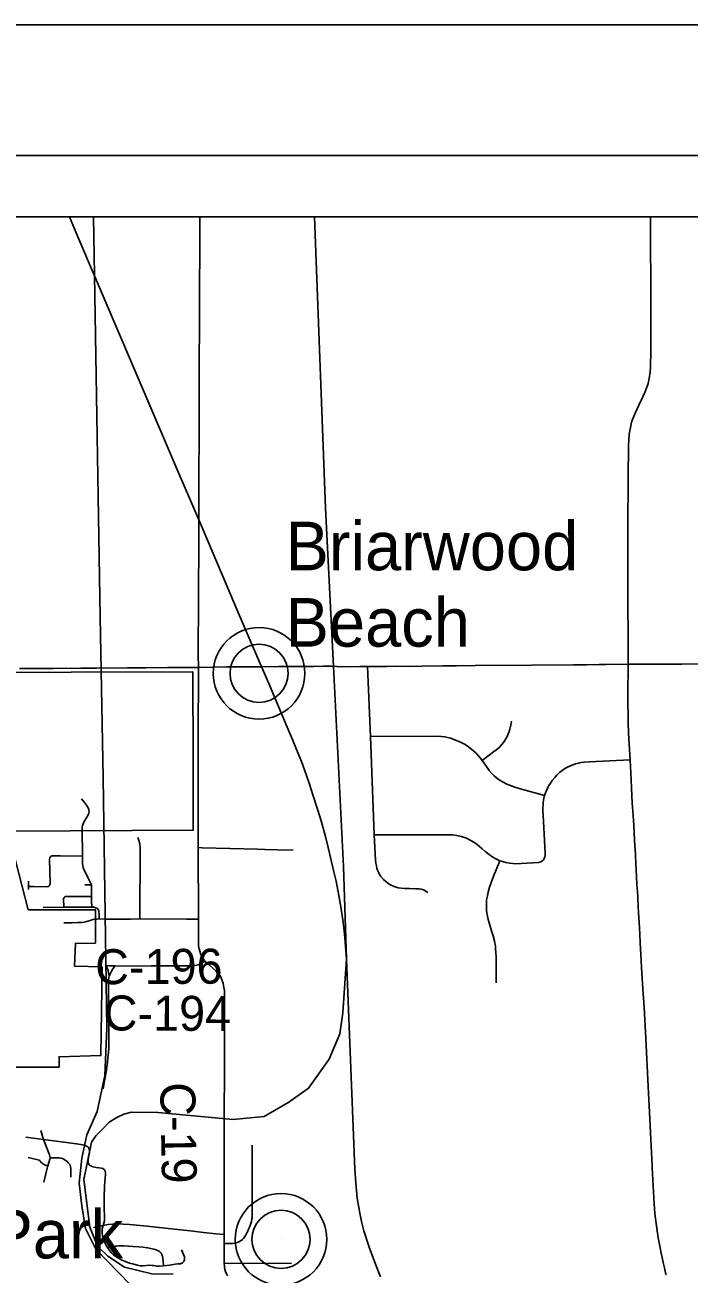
# Model space of a CAD drawing. Extents: x 0 to 34, y 0 to 22.
# Drawn here: x 24.319 to 25.398, y 8.747 to 10.777 of the extents above; entities that cross this region are included whole.
import ezdxf

# ---------------------------------------------------------------- set-up
doc = ezdxf.new("R2010")
doc.units = 0
for name, color, linetype in [('GM_X_Corporation', 7, 'Continuous'), ('GM_X_County_Road', 7, 'Continuous'), ('GM_X_County_Road_Text', 7, 'Continuous'), ('GM_X_Rail_Line', 7, 'Continuous'), ('GM_X_Township_Road', 7, 'Continuous'), ('GM_X_Unincorporated', 7, 'Continuous'), ('GM_X_Unincorporated_Location', 7, 'Continuous'), ('GM_X_Unincorporated_Text', 7, 'Continuous'), ('SH_Data', 7, 'Continuous')]:
    doc.layers.add(name, color=color, linetype=linetype)

msp = doc.modelspace()

# ---------------------------------------------------------------- linework, layer by layer
at = {"layer": 'GM_X_Corporation'}
for points in [[(23.9985, 9.7237), (24.5914, 9.7256), (24.5919, 9.5817), (24.5922, 9.4678), (24.2928, 9.4662)], [(24.2932, 9.4586), (24.3242, 9.3384), (24.4333, 9.3387), (24.4333, 9.2845), (24.401, 9.2841), (24.3995, 9.2472), (24.4443, 9.2458), (24.4421, 9.1017), (24.3743, 9.0997), (24.3743, 9.083), (24.3, 9.083)]]:
    msp.add_lwpolyline(points, dxfattribs=at)
at = {"layer": 'GM_X_County_Road'}
for points in [[(24.6008, 9.8433), (24.6012, 9.943), (24.6012, 9.9715), (24.6017, 10.1839), (24.6025, 10.3332), (24.6027, 10.427), (24.6029, 10.4647)], [(24.6008, 9.7322), (24.6005, 9.7536), (24.6008, 9.8433)], [(24.3101, 9.7306), (24.3258, 9.7307), (24.3649, 9.7308), (24.4097, 9.7312), (24.4179, 9.7313), (24.4352, 9.7313), (24.4856, 9.7319), (24.5155, 9.7321), (24.5502, 9.7323), (24.5828, 9.7322), (24.6008, 9.7322)], [(24.6005, 9.4751), (24.6003, 9.5159), (24.6004, 9.5367), (24.6001, 9.5728), (24.6005, 9.6619), (24.6008, 9.6877), (24.6008, 9.7322)], [(24.6008, 9.7322), (24.6468, 9.7334), (24.6603, 9.7335), (24.6752, 9.7335), (24.6891, 9.7336), (24.7035, 9.7337), (24.7312, 9.7339), (24.7598, 9.7341), (24.7879, 9.7343), (24.8037, 9.7344), (24.8172, 9.7345), (24.8337, 9.7336), (24.8628, 9.7338), (24.8755, 9.7339), (24.9068, 9.7342), (24.9214, 9.7344), (24.944, 9.7343), (24.9636, 9.7347), (24.9969, 9.7351), (25.0198, 9.7352), (25.0503, 9.7354), (25.1423, 9.736), (25.21, 9.7367), (25.2316, 9.737), (25.2518, 9.7371), (25.2632, 9.7372), (25.2989, 9.7376)], [(25.2989, 9.7376), (25.386, 9.7377), (25.561, 9.7385), (25.5754, 9.7381), (25.577, 9.738), (25.5786, 9.7378), (25.5801, 9.7377), (25.5817, 9.7375), (25.5833, 9.7372), (25.5848, 9.737), (25.5864, 9.7367), (25.5879, 9.7364), (25.5894, 9.7361), (25.591, 9.7357), (25.5925, 9.7353), (25.5947, 9.735), (25.5959, 9.7349)], [(24.6481, 8.7439), (24.6465, 8.7469), (24.6449, 8.7508), (24.6438, 8.7542), (24.6431, 8.7571), (24.6429, 8.7592), (24.6426, 8.7635), (24.6423, 8.7802), (24.6424, 8.796), (24.6423, 8.8107), (24.6424, 8.872), (24.6426, 9.0037), (24.6429, 9.0795), (24.6431, 9.1702), (24.643, 9.2), (24.6428, 9.2073), (24.6422, 9.2121), (24.641, 9.2186), (24.6394, 9.2236), (24.6384, 9.2262), (24.6369, 9.2294), (24.6348, 9.2324), (24.6329, 9.235), (24.6307, 9.2375), (24.6287, 9.2395), (24.6241, 9.2435), (24.619, 9.248), (24.611, 9.2553), (24.6077, 9.26), (24.6062, 9.2628), (24.6041, 9.2676), (24.6028, 9.2713), (24.6018, 9.2744), (24.6012, 9.2775), (24.6009, 9.2803), (24.6008, 9.3094), (24.6008, 9.3234), (24.6005, 9.4397), (24.6005, 9.4751)], [(24.3823, 9.3173), (24.3955, 9.3174), (24.4049, 9.3177), (24.4105, 9.318), (24.4151, 9.3186), (24.4192, 9.3196), (24.4262, 9.3219), (24.4293, 9.3227), (24.432, 9.3232)], [(24.432, 9.3232), (24.4324, 9.3233), (24.4358, 9.3236), (24.4396, 9.3237), (24.4511, 9.3236), (24.4712, 9.3233), (24.4904, 9.3236), (24.5056, 9.3237), (24.5812, 9.3236), (24.6008, 9.3234)], [(24.4509, 9.2479), (24.4564, 9.2475), (24.4606, 9.2474), (24.4656, 9.2473), (24.5025, 9.2472), (24.524, 9.2474), (24.5914, 9.2478), (24.5949, 9.2481), (24.598, 9.2486), (24.6004, 9.2493), (24.6027, 9.2502), (24.6046, 9.2514), (24.611, 9.2553)]]:
    msp.add_lwpolyline(points, dxfattribs=at)
at = {"layer": 'GM_X_Rail_Line'}
msp.add_line((24.4318, 10.3698), (24.4302, 10.4647), dxfattribs=at)
for points in [[(24.8962, 8.7422), (24.8883, 8.7629), (24.8781, 8.7904), (24.8693, 8.8167), (24.8654, 8.832), (24.8627, 8.8454), (24.8588, 8.8698), (24.8565, 8.895), (24.855, 8.9173), (24.8414, 9.2584), (24.8382, 9.2995), (24.8365, 9.3144), (24.8343, 9.3292), (24.832, 9.3436), (24.8286, 9.3621), (24.8242, 9.3851), (24.8208, 9.4005), (24.8154, 9.4235), (24.8114, 9.4398), (24.8074, 9.4556), (24.8, 9.4833), (24.7943, 9.5021), (24.7867, 9.5255), (24.781, 9.543), (24.7757, 9.5583), (24.7679, 9.5794), (24.7601, 9.5993), (24.7536, 9.6153), (24.7451, 9.6356), (24.7165, 9.7026), (24.685, 9.7762), (24.6653, 9.8218), (24.6035, 9.9675), (24.5689, 10.0479), (24.5078, 10.1914), (24.432, 10.3692), (24.4049, 10.4323), (24.391, 10.4647)], [(24.8412, 9.2589), (24.8364, 9.409), (24.8203, 9.7338), (24.8069, 9.9916), (24.7893, 10.4647)], [(24.4892, 8.7302), (24.4338, 8.7869), (24.4173, 8.8209), (24.4111, 8.8573), (24.407, 8.8945), (24.4111, 8.9352), (24.4194, 8.9729), (24.4361, 9.011), (24.4487, 9.0691), (24.4521, 9.1459), (24.4461, 9.5537), (24.441, 9.8141), (24.4318, 10.3698)], [(24.5599, 8.7463), (24.5252, 8.7467), (24.4806, 8.7579), (24.4537, 8.7755), (24.437, 8.7917), (24.4245, 8.823), (24.4147, 8.9004), (24.4271, 8.961), (24.434, 8.9711), (24.4443, 8.9817), (24.4555, 8.9932), (24.4679, 9.0009), (24.4794, 9.0064), (24.4922, 9.0095), (24.5346, 9.0092), (24.6571, 8.9977), (24.7075, 9.0026), (24.7477, 9.0259), (24.7796, 9.0488), (24.8132, 9.0961), (24.8302, 9.1371), (24.8353, 9.171), (24.8412, 9.2589)]]:
    msp.add_lwpolyline(points, dxfattribs=at)
at = {"layer": 'GM_X_Township_Road'}
for p, q in [((24.4161, 9.3793), (24.4268, 9.3794)), ((24.6426, 8.7635), (24.752, 8.7641))]:
    msp.add_line(p, q, dxfattribs=at)
for points in [[(25.2989, 9.7376), (25.2986, 9.7728), (25.2985, 9.804), (25.2984, 9.8165), (25.2983, 9.8418), (25.2982, 9.8565), (25.298, 9.9073), (25.2982, 9.945), (25.2983, 9.964), (25.2984, 9.9939), (25.2985, 10.0062), (25.2989, 10.0562), (25.2991, 10.0777), (25.2992, 10.0866), (25.2995, 10.0945), (25.2998, 10.1006), (25.3001, 10.1058), (25.3003, 10.1087), (25.3005, 10.111), (25.3009, 10.1145), (25.302, 10.12), (25.3029, 10.1251), (25.3043, 10.1309), (25.3059, 10.1357), (25.3073, 10.1392), (25.3101, 10.1457), (25.3161, 10.1588), (25.3219, 10.171), (25.3253, 10.1785), (25.327, 10.1823), (25.3281, 10.1853), (25.33, 10.1907), (25.331, 10.1939), (25.3319, 10.197), (25.3325, 10.1995), (25.333, 10.2022), (25.3336, 10.2058), (25.334, 10.2089), (25.3343, 10.2117), (25.3347, 10.2152), (25.335, 10.2186), (25.3352, 10.2233), (25.3357, 10.245), (25.3355, 10.2904), (25.3356, 10.3142), (25.3354, 10.3584), (25.3353, 10.4193), (25.3351, 10.4647)], [(24.9733, 9.3667), (24.9672, 9.3703), (24.9647, 9.3714), (24.9624, 9.3723), (24.9595, 9.3727), (24.9535, 9.3729), (24.9438, 9.373), (24.9354, 9.3732), (24.9302, 9.3736), (24.925, 9.3745), (24.9203, 9.3758), (24.9159, 9.3774), (24.9107, 9.3804), (24.9054, 9.3841), (24.9012, 9.388), (24.8971, 9.3927), (24.8944, 9.3971), (24.8931, 9.3999), (24.8918, 9.4028), (24.8907, 9.406), (24.8897, 9.4099), (24.889, 9.4144), (24.8885, 9.4192), (24.8863, 9.4602), (24.8814, 9.5918), (24.8804, 9.6202), (24.8755, 9.7339)], [(25.3606, 8.7451), (25.3596, 8.7488), (25.3577, 8.7567), (25.3557, 8.7653), (25.3538, 8.7734), (25.3523, 8.7808), (25.3506, 8.7893), (25.3491, 8.7974), (25.3477, 8.8053), (25.3464, 8.8133), (25.3452, 8.8212), (25.344, 8.8287), (25.3429, 8.8371), (25.3421, 8.845), (25.3414, 8.8533), (25.3408, 8.8608), (25.3379, 8.9191), (25.3378, 8.9224), (25.3356, 8.9659), (25.3338, 8.9991), (25.3313, 9.0514), (25.3272, 9.1297), (25.3245, 9.1804), (25.3226, 9.2098), (25.3203, 9.2448), (25.3197, 9.2558), (25.3182, 9.2856), (25.3175, 9.2984), (25.3169, 9.3095), (25.3165, 9.3183), (25.3158, 9.3331), (25.3145, 9.3571), (25.3143, 9.361), (25.3131, 9.3805), (25.3119, 9.4042), (25.3114, 9.413), (25.3104, 9.428), (25.3099, 9.4359), (25.309, 9.4519), (25.3077, 9.476), (25.3063, 9.4991), (25.3055, 9.5117), (25.3041, 9.5368), (25.3034, 9.55), (25.3018, 9.5824), (25.2995, 9.6252), (25.2988, 9.6439), (25.2985, 9.6548), (25.2982, 9.6751), (25.2983, 9.6936), (25.2987, 9.7313), (25.2988, 9.7347), (25.2989, 9.7376)], [(25.0617, 9.5813), (25.0802, 9.5954), (25.0852, 9.5991), (25.0896, 9.6028), (25.093, 9.6065), (25.0961, 9.6104), (25.0983, 9.6137), (25.1006, 9.6174), (25.102, 9.6205), (25.1039, 9.6246), (25.1053, 9.6283), (25.1064, 9.632), (25.108, 9.6388), (25.1092, 9.6451)], [(24.8804, 9.6202), (24.9826, 9.6209), (24.9955, 9.6202), (25.0011, 9.6196), (25.0101, 9.6176), (25.0174, 9.6151), (25.0237, 9.6124), (25.0286, 9.6101), (25.0327, 9.6077), (25.037, 9.6051), (25.045, 9.599), (25.0513, 9.5935), (25.0553, 9.5894), (25.0588, 9.5852), (25.0617, 9.5813), (25.0684, 9.5714), (25.073, 9.5652), (25.0773, 9.5603), (25.0813, 9.5565), (25.0855, 9.5527), (25.0911, 9.5488), (25.0968, 9.5455), (25.1014, 9.543), (25.1077, 9.5404), (25.1147, 9.5379), (25.1219, 9.5355), (25.1627, 9.5242)], [(25.1599, 9.4185), (25.1612, 9.42), (25.1625, 9.422), (25.1632, 9.4246), (25.1637, 9.4276), (25.1639, 9.4305), (25.1606, 9.4925), (25.1603, 9.4996), (25.1602, 9.5045), (25.1605, 9.5097), (25.1607, 9.5129), (25.1612, 9.5163), (25.1618, 9.52), (25.1627, 9.5242), (25.1644, 9.5287), (25.1665, 9.5337), (25.1683, 9.5376), (25.1699, 9.5405), (25.1724, 9.5446), (25.1754, 9.5489), (25.1794, 9.5537), (25.1827, 9.5573), (25.1874, 9.5616), (25.1939, 9.5664), (25.1981, 9.5692), (25.2014, 9.5709), (25.205, 9.5726), (25.2089, 9.5741), (25.213, 9.5756), (25.2179, 9.577), (25.2224, 9.5779), (25.2273, 9.5786), (25.2362, 9.5791), (25.3018, 9.5824)], [(24.4125, 9.4754), (24.4134, 9.4783), (24.4144, 9.4808), (24.4194, 9.4893), (24.4219, 9.4939), (24.4227, 9.4961), (24.423, 9.4984), (24.4228, 9.5008), (24.422, 9.5035), (24.4207, 9.5062), (24.4189, 9.5087), (24.4154, 9.5131), (24.4105, 9.5188)], [(24.4274, 9.343), (24.4272, 9.3521), (24.427, 9.36), (24.4269, 9.3749), (24.4268, 9.3794), (24.4248, 9.3833), (24.4232, 9.3865), (24.4208, 9.3913), (24.4181, 9.3969), (24.4157, 9.4018), (24.414, 9.4058), (24.4134, 9.4075), (24.4129, 9.4101), (24.4125, 9.4139), (24.4123, 9.426), (24.412, 9.4695), (24.4121, 9.4723), (24.4125, 9.4754)], [(24.8863, 9.4602), (24.9149, 9.4603), (25.0042, 9.4606), (25.0139, 9.4603), (25.0199, 9.4596), (25.0281, 9.4578), (25.0363, 9.4548), (25.0441, 9.4508), (25.0497, 9.4477), (25.0535, 9.445), (25.0614, 9.4379), (25.0667, 9.4331), (25.0729, 9.4283), (25.079, 9.4242), (25.0849, 9.4211), (25.0905, 9.4184), (25.0947, 9.4169), (25.0998, 9.4155), (25.1061, 9.4144), (25.1112, 9.4138), (25.1161, 9.4135), (25.1249, 9.4137), (25.1531, 9.4154), (25.1554, 9.4158), (25.1579, 9.4169), (25.1599, 9.4185)], [(24.5056, 9.3237), (24.506, 9.4384), (24.5058, 9.4411), (24.5056, 9.4432), (24.5053, 9.4456), (24.504, 9.4512), (24.5025, 9.4562)], [(24.6005, 9.4397), (24.6067, 9.4395), (24.6964, 9.4373), (24.7085, 9.4367), (24.7288, 9.4362), (24.7545, 9.4356)], [(24.3586, 9.378), (24.3592, 9.379), (24.3595, 9.3802), (24.3596, 9.3811), (24.3587, 9.4211), (24.3591, 9.4232), (24.3596, 9.4241), (24.3601, 9.4248), (24.3608, 9.4252), (24.3616, 9.4256)], [(24.3616, 9.4256), (24.3632, 9.4262), (24.3652, 9.4264), (24.3767, 9.4263), (24.4123, 9.426)], [(25.0843, 9.2201), (25.0844, 9.2551), (25.0843, 9.2612), (25.0839, 9.2699), (25.0835, 9.2758), (25.083, 9.2801), (25.0823, 9.2842), (25.0816, 9.2882), (25.0796, 9.2961), (25.0769, 9.3044), (25.0746, 9.3118), (25.0728, 9.3173), (25.0713, 9.3231), (25.0701, 9.3281), (25.0693, 9.3332), (25.0688, 9.3379), (25.0687, 9.3428), (25.0686, 9.3469), (25.0687, 9.3509), (25.0689, 9.3548), (25.07, 9.3614), (25.0715, 9.3674), (25.0737, 9.3752), (25.0797, 9.3917), (25.0855, 9.4061), (25.0905, 9.4184)], [(24.3248, 9.3716), (24.3247, 9.3741), (24.3246, 9.3767), (24.3247, 9.3814), (24.3247, 9.3853)], [(24.3246, 9.3767), (24.333, 9.3765), (24.3546, 9.376), (24.3561, 9.3763), (24.3573, 9.3767), (24.3582, 9.3774), (24.3586, 9.378)], [(24.3821, 9.3427), (24.3817, 9.3565), (24.382, 9.3578), (24.3825, 9.3585), (24.3832, 9.3593)], [(24.3832, 9.3593), (24.3847, 9.36), (24.3863, 9.3603), (24.388, 9.3604), (24.427, 9.36)], [(24.3485, 9.3424), (24.3821, 9.3427), (24.4274, 9.343), (24.4311, 9.3427), (24.4325, 9.3424), (24.4336, 9.342), (24.4358, 9.3412), (24.4373, 9.3402)], [(24.4396, 9.3237), (24.4393, 9.3317), (24.4391, 9.3356), (24.4388, 9.3372), (24.4385, 9.3382), (24.438, 9.3393), (24.4373, 9.3402)], [(24.4557, 9.2307), (24.4546, 9.236), (24.4538, 9.2395), (24.453, 9.2426), (24.4509, 9.2479)], [(24.4557, 9.2307), (24.4566, 9.233), (24.4576, 9.2356), (24.4596, 9.2391), (24.4619, 9.2424), (24.4656, 9.2473)], [(24.4457, 9.0477), (24.4478, 9.0577), (24.4493, 9.066), (24.4507, 9.0749), (24.4518, 9.0831), (24.4528, 9.0912), (24.4537, 9.0986), (24.4544, 9.1065), (24.4549, 9.1136), (24.455, 9.1213), (24.455, 9.1684), (24.4549, 9.1767), (24.4548, 9.1872), (24.4546, 9.2031), (24.4545, 9.214), (24.4547, 9.2248), (24.4552, 9.2285), (24.4557, 9.2307)], [(24.3495, 8.8958), (24.3549, 8.9188), (24.3554, 8.9206), (24.3561, 8.9225), (24.3578, 8.9277), (24.3595, 8.9333), (24.3598, 8.9355), (24.3594, 8.938), (24.3588, 8.9402), (24.349, 8.9654), (24.348, 8.9687), (24.3448, 8.9801)], [(24.446, 8.8257), (24.4483, 8.8333), (24.448, 8.8423), (24.4474, 8.8511), (24.4473, 8.859), (24.4475, 8.8711), (24.4483, 8.8899), (24.4492, 8.9031), (24.4495, 8.9086), (24.4496, 8.9113), (24.4493, 8.9134), (24.4485, 8.9152), (24.4475, 8.9167), (24.4456, 8.9179), (24.4433, 8.9185), (24.4347, 8.9199), (24.4296, 8.921), (24.4271, 8.9217), (24.4251, 8.9225), (24.4236, 8.9235), (24.4225, 8.9247), (24.4219, 8.9264), (24.4215, 8.9284), (24.4216, 8.9314), (24.4223, 8.9377), (24.4235, 8.9434), (24.4239, 8.9461), (24.4234, 8.9502), (24.4224, 8.9518), (24.4211, 8.9534), (24.419, 8.9547), (24.4151, 8.9559), (24.4098, 8.957), (24.4028, 8.9584), (24.349, 8.9654), (24.3203, 8.969)], [(24.6739, 8.8042), (24.6751, 8.8058), (24.6762, 8.8077), (24.6778, 8.8105), (24.6794, 8.8137), (24.6809, 8.8165), (24.6822, 8.8195), (24.6837, 8.8227), (24.6854, 8.8272), (24.6868, 8.8318), (24.6876, 8.8357), (24.6878, 8.8376), (24.6879, 8.8399), (24.688, 8.8443), (24.6882, 8.8947), (24.6882, 8.956)], [(24.3243, 8.9361), (24.3312, 8.9344), (24.3397, 8.9324), (24.342, 8.9315), (24.343, 8.931), (24.3438, 8.9303), (24.3455, 8.9281), (24.3465, 8.9271), (24.3475, 8.9261), (24.3489, 8.9251), (24.3504, 8.9242), (24.3517, 8.9237), (24.3531, 8.9232), (24.3546, 8.9228), (24.3561, 8.9225)], [(24.3598, 8.9355), (24.3648, 8.9356), (24.3686, 8.9356), (24.372, 8.9356), (24.3745, 8.9354), (24.3772, 8.9351), (24.3799, 8.9343), (24.3822, 8.9331), (24.3844, 8.9316), (24.3862, 8.9303), (24.3874, 8.9294), (24.3887, 8.9282), (24.3898, 8.9268), (24.391, 8.9252), (24.3921, 8.923), (24.393, 8.9207), (24.3934, 8.9184), (24.3936, 8.9158), (24.3935, 8.904)], [(24.43, 8.8223), (24.446, 8.8257), (24.4541, 8.8269), (24.4609, 8.8277), (24.4691, 8.8281), (24.4787, 8.8279), (24.4889, 8.8271), (24.5175, 8.8242), (24.5467, 8.821), (24.5873, 8.8166), (24.6088, 8.814), (24.629, 8.8118), (24.6423, 8.8107)], [(24.446, 8.8257), (24.4445, 8.8204), (24.4441, 8.8173), (24.4443, 8.8135), (24.4451, 8.8083), (24.4464, 8.8031), (24.4481, 8.7986), (24.4496, 8.7953), (24.4531, 8.7898), (24.4569, 8.7843), (24.4591, 8.7815), (24.4606, 8.7799), (24.4626, 8.7781), (24.4657, 8.7757), (24.4702, 8.7729), (24.4763, 8.7693), (24.482, 8.7668), (24.4885, 8.7644), (24.4959, 8.7625), (24.5016, 8.7609), (24.5058, 8.7602), (24.5109, 8.76), (24.5162, 8.7605), (24.5212, 8.7608), (24.5253, 8.7607), (24.5278, 8.7605), (24.5303, 8.7601), (24.5326, 8.7596), (24.5347, 8.7593), (24.537, 8.7592), (24.544, 8.7599), (24.554, 8.7612), (24.5629, 8.7625), (24.5675, 8.763), (24.5713, 8.7634), (24.5724, 8.7637), (24.5727, 8.7638), (24.5746, 8.7648), (24.5749, 8.765), (24.575, 8.7651), (24.5753, 8.7654), (24.5757, 8.7657), (24.5758, 8.7658), (24.5759, 8.7659), (24.5762, 8.7663), (24.5763, 8.7664), (24.5764, 8.7665), (24.5765, 8.7666), (24.5766, 8.7667), (24.5768, 8.767), (24.5769, 8.7671), (24.577, 8.7673), (24.5772, 8.7677), (24.5773, 8.7678), (24.5774, 8.7679), (24.5775, 8.7681), (24.5776, 8.7683), (24.5777, 8.7686), (24.5782, 8.7703), (24.5783, 8.7709), (24.5781, 8.7744), (24.5732, 8.786)], [(24.4531, 8.7898), (24.4602, 8.7912), (24.4624, 8.7915), (24.4654, 8.7918), (24.4682, 8.792), (24.4713, 8.7922), (24.4759, 8.7923), (24.4801, 8.7922), (24.4943, 8.7916), (24.5039, 8.7908), (24.5105, 8.7902), (24.518, 8.7893), (24.5233, 8.7884), (24.528, 8.7873), (24.532, 8.7861), (24.5353, 8.7846), (24.5377, 8.7832)], [(24.6424, 8.796), (24.6485, 8.7961), (24.6534, 8.7962), (24.656, 8.7964), (24.6588, 8.7968), (24.6622, 8.7975), (24.6643, 8.798), (24.6663, 8.7988), (24.67, 8.8009), (24.6721, 8.8025), (24.6739, 8.8042)], [(24.544, 8.7599), (24.5435, 8.7678), (24.5429, 8.7723), (24.5424, 8.7752), (24.5414, 8.7782), (24.54, 8.7808), (24.5387, 8.7823), (24.5377, 8.7832)]]:
    msp.add_lwpolyline(points, dxfattribs=at)
at = {"layer": 'GM_X_Unincorporated'}
for centre, radius in [((24.6992, 9.7229), 0.0744), ((24.6992, 9.7229), 0.0472), ((24.7349, 8.803), 0.0744), ((24.7349, 8.803), 0.0472)]:
    msp.add_circle(centre, radius, dxfattribs=at)
at = {"layer": 'GM_X_Unincorporated_Location'}
for p, q in [((24.6992, 9.7229), (24.6992, 9.7229)), ((24.7349, 8.803), (24.7349, 8.803))]:
    msp.add_line(p, q, dxfattribs=at)
at = {"layer": 'SH_Data'}
for p, q in [((27.4004, 10.7767), (23.0475, 10.7767)), ((15.7135, 10.5647), (26.49, 10.5647)), ((22.6135, 10.4647), (26.39, 10.4647))]:
    msp.add_line(p, q, dxfattribs=at)

# ---------------------------------------------------------------- texts
at = {"layer": 'GM_X_County_Road_Text'}
for s, rotation, p in [('C-196', 0.274, (24.4331, 9.2176)), ('C-194', 359.7247, (24.4467, 9.1426)), ('C-19', 271.0299, (24.5385, 9.0579))]:
    msp.add_text(s, height=0.05682, rotation=rotation, dxfattribs=at).set_placement(p)
at = {"layer": 'GM_X_Unincorporated_Text'}
for s, height, p in [('Briarwood', 0.07898, (24.7422, 9.8904)), ('Beach', 0.07898, (24.7422, 9.7663)), ('Chippewa Lake Park', 0.078977, (23.5039, 8.7721))]:
    msp.add_text(s, height=height, rotation=0, dxfattribs=at).set_placement(p)

doc.saveas('drawing.dxf')
